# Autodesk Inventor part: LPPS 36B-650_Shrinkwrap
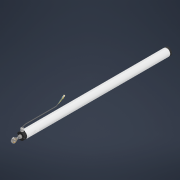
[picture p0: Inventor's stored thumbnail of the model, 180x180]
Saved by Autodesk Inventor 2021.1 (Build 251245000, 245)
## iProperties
Created: 2020-09
Part Number: LPPS 36B-650_Shrinkwrap
Material: Generic
Document SubType Name: Modeling
Designer: J. Nielson
Density: 1 g/cm^3
Appearance: Default
Author: J. Nielson
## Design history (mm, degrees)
derived "LPPS 36B-650.iam"
body "Solid1"
node "LPPS 36B Cable End Cap.iam:1::LPPS-36B PLASTIC CABLE END.ipt"
node "LPPS 36B Cable End Cap.iam:1::LPPS 36B- Cable Gland.ipt:1"
body "Solid2"
node "LPPS 36B Cable End Cap.iam:1::Cable Gland Cap.ipt:1"
body "Solid3"
node "LPPS 36B Cable End Cap.iam:1::Cable.ipt:1"
body "Solid4"
node "LPPS 36B Cable End Cap.iam:1::Cable Gland Seal 1 of 2.ipt:1"
body "Solid5"
node "LPPS 36B Cable End Cap.iam:1::Cable Gland 2 of 2.ipt:1"
body "Solid6"
node "LPPS 36B Cable End Cap.iam:1::#6 Terminal Ring 22 - 18 AWG.i"
body "Solid7"
node "LPPS-36B-650 METAL HOUSING.ipt:1"
body "Solid8"
node "MALE Rod Eye SW.ipt:1"
body "Solid9"
node "LPPS-36B PLASTIC STROKE END.ipt:1"
body "Solid10"
node "LPPS-36B-650 Back Stop.ipt:1"
body "Solid11"
node "LPPS-36B-650 Front Stop.ipt:1"
body "Solid12"
node "AS 1427 - M3 x 16.ipt:1"
body "Solid13"
node "AS 1427 - M3 x 16.ipt:2"
body "Solid14"
node "AS 1427 - M3 x 16.ipt:3"
body "Solid15"
node "AS 1427 - M3 x 16.ipt:4"
body "Solid16"
node "AS 1112 - M8  Type 5.ipt:1"
body "Solid17"
node "AS 1237 - 8.ipt:1"
body "Solid18"
node "AS 1968 - 1976 - 8.ipt:1"
body "Solid19"
